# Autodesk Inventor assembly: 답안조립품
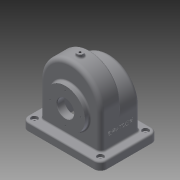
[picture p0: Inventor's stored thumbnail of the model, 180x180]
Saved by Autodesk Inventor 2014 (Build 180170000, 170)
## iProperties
Created: 2017-11
Part Number: 답안조립품
Document SubType Name: Assembly
Designer: net
Author: net
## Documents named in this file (2)
- C:\Users\net\Desktop\471107V1024\답안조립품.iam
- C:\Users\net\Desktop\471107V1024\본체.ipt
